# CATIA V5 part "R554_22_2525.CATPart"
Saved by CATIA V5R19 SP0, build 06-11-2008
Material "Steel": density 7860 kg/m3, Young's modulus 2e+11 Pa, Poisson ratio 0.266, thermal expansion 1.17e-05 1/K
Bounding box of the stored display mesh (mm): x -12.582 to 12.582, y -12.358 to 12.439, z 0.001 to 96
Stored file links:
  G:\Podręcznik\CD\Narzędzia\Arkusz Excel\Modele narzędzi\R554.22-2525.CATPart
  C:\Program Files\Dassault Systemes\B19\intel_a\startup\materials\Catalog.CATMaterial
  F:\OSTATNIE\DesignTable_R.xls
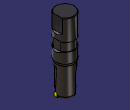
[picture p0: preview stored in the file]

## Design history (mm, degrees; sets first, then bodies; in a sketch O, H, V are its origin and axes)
Parameters
  CuttingType = "CUTTER"
  d = 25 mm {design table}
  D = 25 mm {design table}
  L = 96 mm {design table}
  l = 56 mm {design table}
  alfa = 15 deg {design table}
  gammap = 4 deg {design table}
  S = 3.18 mm {design table}
  rp = 5 mm
  x = 0.6282 mm {design table}
  gammaf = -2 deg {design table}
  z = 2 {design table}
  kat_miedzy_plytkami = 180 deg {design table}
  `dp'` = 9.9756 mm
Body1 "HOLDER" (main body), material "Steel"
  Sketch1 "sketch" on yz-plane, origin (0, 0, 0), H (0, 1, 0), V (0, 0, 1)
    line L1 (0, 0.6282) -> (7.5, 0.6282)
    line L2 (11.5, 4.6282) -> (11.5, 40)
    point P2 (11.5, 40)
    line L3 (11.5, 40) -> (11.5, 40)
    point P3 (12.5, 40)
    line L4 (12.5, 43.2077) -> (12.5, 56.8)
    point P4 (12.5, 56.8)
    line L5 (12.5, 56.8) -> (11.5, 56.8)
    line L6 (11.5, 56.8) -> (11.5, 68)
    line L7 (11.5, 68) -> (12.5, 68)
    point P7 (12.5, 68)
    line L8 (12.5, 68) -> (12.5, 95.2929)
    line L9 (12.5, 95.2929) -> (11.7929, 96)
    line L10 (11.7929, 96) -> (0, 96)
    point P10 (0, 96)
    line L11 (0, 96) -> (0, 0.6282)
    construction line L12 (0, -29.1199) -> (0, 199.3445)
    point P11 (0, -29.1199)
    line L13 (11.5, 40) -> (12.5, 43.2077)
    point P13 (11.5, 40)
    arc A1 centre (7.5, 4.6282) radius 4 from (11.5, 4.6282) to (7.5, 0.6282) cw
    point P17 (7.5, 4.6282)
    length L6 = 11.2 {= 0.2*l}
    distance P2 H = 40 {= L-l}
    length L9 = 1
    angle L8 L9 = 45
    distance L6 L8 = 1
    distance L8 L11 = 12.5 {= d/2}
    distance L10 L7 = 28 {= 0.5*l}
    distance P3 P4 = 16.8 {= 0.3*l}
    length L13 = 3.36 {= 0.2*(0.3*l)}
    distance L1 H = 0.6282 {= x}
    radius A1 = 4 {= 0.8*rp}
    distance P17 L11 = 7.5 {= D/2-rp}
    vertical: L2 V, L4 V, L6 V, L8 V, L11 V, L12 V
    horizontal: L3 H, L5 H, L7 H, L10 H
    coincidence: P7 L4, P10 V, P11 V, L3 P3, L4 P3, P2 P13
    tangency: A1 L2, A1 L1
  Shaft1: profile Sketch1, axis Z axis, angle 360
  Plane1: type Offset, Offset 2, RefPlane zx-plane
  Sketch2 on Plane1, origin (0, 2, 0), H (-1, 0, 0), V (0, 0, 1)
    line L1 (0, 0) -> (4.2605, 0)
    horizontal: L1 H
  Plane2 "gammap": type Angle, Angle -4 {= -gammap}, Direction Sketch2, RefPlane Plane1
  Sketch3 on zx-plane, origin (0, 0, 0), H (-1, 0, 0), V (0, 0, 1)
    line L1 (-10.5, 96) -> (-10.5, 77.6)
    line L2 (-10.5, 77.6) -> (-12.5, 75.6)
    line L3 (-12.5, 75.6) -> (-12.5, 70)
    line L4 (-12.5, 70) -> (-10.5, 68)
    point P5 (-10.5, 68)
    line L5 (-10.5, 68) -> (-10.5, 56.8)
    point P6 (-10.5, 56.8)
    line L6 (-10.5, 56.8) -> (-12.5, 54.8)
    point P7 (-12.5, 54.8)
    line L7 (-12.5, 54.8) -> (-16.5, 54.8)
    line L8 (-16.5, 54.8) -> (-16.5, 96)
    line L9 (-16.5, 96) -> (-10.5, 96)
    reference projected line E1 (-9.2929, 96) -> (9.2929, 96) from edge [face of Shaft1 from Sketch1.L9 | face of Shaft1 from Sketch1.L10]
    reference projected line E2 (-10, 68) -> (10, 68) from edge [face of Shaft1 from Sketch1.L7 | face of Shaft1 from Sketch1.L8]
    reference projected line E3 (-10, 56.8) -> (10, 56.8) from edge [face of Shaft1 from Sketch1.L4 | face of Shaft1 from Sketch1.L5]
    reference projected line E4 through (0, 0) direction (0, 1) from axis of face of Shaft1 from Sketch1.L8
    distance L3 L1 = 2
    angle L2 L1 = 45
    angle L6 L5 = 45
    distance L1 L8 = 6
    distance E4 L3 = 12.5 {= d/2}
    distance P7 L5 = 2
    length L3 = 5.6 {= 0.1*l}
    vertical: L1 V, L3 V, L5 V, L8 V
    perpendicularity: L4 L2
    coincidence: P7 L3, L9 E1, P5 E2, P6 E3
    horizontal: L7 H, L9 H
  Pocket1: profile Sketch3, direction (0, -1, 0), length 20, mirrored extent
  Sketch4 on Plane2, origin (0, 1.9903, 0.1392), H (-1, 0, 0), V (0, -0.0698, 0.9976)
    line L1 (12.5, 13.7491) -> (12.5, 0)
    point P1 (12.5, 0)
    distance V L1 = 12.5 {= D/2}
    coincidence: P1 H
    vertical: L1 V
  Plane3 "gammaf": type Angle, Angle -2 {= gammaf}, Direction Sketch4, RefPlane Plane2
  Plane4: type Offset, Offset 12.5 {= D/2}, RefPlane zx-plane
  Sketch5 on Plane4, origin (0, 12.5, 0), H (-1, 0, 0), V (0, 0, 1)
    point P1 (2.5, 0)
    line L1 (2.5, 0) -> (2.5, 25.1678)
    arc A1 centre (14.5, 25.1678) radius 12 from (2.5, 25.1678) to (12.5, 37) cw
    point P4 (12.5, 37)
    line L2 (12.5, 37) -> (12.5, 0)
    point P5 (12.5, 0)
    line L3 (12.5, 0) -> (2.5, 0)
    reference projected point E1 (0, 4.6282) from edge
    reference projected line E2 (-11.5, 40) -> (11.5, 40) from edge [face of Shaft1 from Sketch1.L2 | face of Shaft1 from Sketch1.L13]
    distance E1 L2 = 12.5 {= D/2}
    radius A1 = 12
    distance E2 P4 = 3
    distance L1 L2 = 10 {= 2*rp}
    coincidence: P1 H, P5 H
    vertical: L1 V, L2 V
    horizontal: L3 H
    tangency: A1 L1
  Pocket2: profile Sketch5, direction (0, -1, 0), up to Plane3
  CircPattern1: of Pocket2, instances 2 {= z}, angular step 180 {= kat_miedzy_plytkami}, axis from Z axis
  Sketch6 on Plane3, origin (-0.0848, 2.4228, 0.1694), H (-0.9994, -0.035, 0), V (0.0024, -0.0697, 0.9976)
    line L1 (12.5, 0) -> (12.5, 6.1909)
    point P1 (12.5, 0)
    distance V L1 = 12.5 {= D/2}
    coincidence: P1 H
    vertical: L1 V
  Plane5: type Angle, Angle 90, Direction Sketch6, RefPlane Plane3
  Plane6: type Offset, Offset 5 {= rp}, RefPlane Plane5, reversed
  Sketch7 on Plane6, origin (-7.4954, -0.2624, 0), H (0.035, -0.9994, 0), V (0, 0, 1)
    point P1 (-2.9373, 0)
    line L1 (-2.9373, 0) -> (-2.5887, 4.9878)
    line L2 (-2.5887, 4.9878) -> (0.5835, 4.7661)
    line L3 (0.5835, 4.7661) -> (0.2944, 0.6283)
    line L4 (0.2944, 0.6283) -> (-2.9373, 0)
    axis line L5 (-2.9373, 0) -> (2.8409, -0.4038)
    reference projected line E1 (-0.6773, 25.1678) -> (-2.4361, 0) from edge [end face of Pocket2 | face of Pocket2 from Sketch5.L1]
    reference projected line E2 (-0.6773, 25.1678) -> (-2.4361, 0) from edge [end face of Pocket2 | face of Pocket2 from Sketch5.L1]
    distance L1 L3 = 3.18 {= S}
    length L1 = 5 {= rp}
    angle L5 L4 = 15 {= alfa}
    distance L1 E2 = 0.5
    coincidence: P1 H
    perpendicularity: L2 L1
    parallelism: L5 L2, L1 E1
  Groove1: profile Sketch7, axis Sketch7.L2, angle 360
  CircPattern2: of Groove1, instances 2 {= z}, angular step 180 {= kat_miedzy_plytkami}, axis from Z axis
Body2 "CUTTER"
  Sketch8 "CUT" on yz-plane, origin (0, 0, 0), H (0, 1, 0), V (0, 0, 1)
    point P1 (7.5, 5)
    point P2 (0, 0.6282)
    line L1 (0, 0.6282) -> (5.0737, 0.6282)
    arc A1 centre (7.5, 5) radius 5 from (5.0737, 0.6282) to (11.5, 8) ccw
    point P4 (7.5, 5)
    point P5 (11.5, 8)
    line L2 (11.5, 8) -> (0, 8)
    point P6 (0, 8)
    line L3 (0, 8) -> (0, 0.6282)
    axis line L4 (0, 8) -> (12.5, 8)
    point P7 (12.5, 8)
    distance P1 H = 5 {= rp}
    distance P1 V = 7.5 {= D/2-rp}
    distance H L1 = 0.6282 {= x}
    length L4 = 12.5 {= D/2}
    distance P7 P5 = 1
    coincidence: P2 V, P6 V, P4 P1
    horizontal: L1 H, L2 H, L4 H
    vertical: L3 V
    tangency: A1 H
  Sketch9 "NOCUT" on yz-plane, origin (0, 0, 0), H (0, 1, 0), V (0, 0, 1)
    point P1 (0, 8)
    line L1 (0, 8) -> (11.5, 8)
    point P2 (11.5, 8)
    line L2 (11.5, 8) -> (11.5, 40)
    line L3 (11.5, 40) -> (12.5, 40)
    line L4 (12.5, 40) -> (12.5, 56.8)
    line L5 (12.5, 56.8) -> (11.5, 56.8)
    line L6 (11.5, 56.8) -> (11.5, 68)
    line L7 (11.5, 68) -> (12.5, 68)
    point P8 (12.5, 68)
    line L8 (12.5, 68) -> (12.5, 96)
    line L9 (12.5, 96) -> (0, 96)
    point P10 (0, 96)
    line L10 (0, 96) -> (0, 8)
    reference projected line E1 (11.5, 8) -> (0, 8) from Sketch8.L2
    reference projected point E2 (11.5, 8) from vertex [element of Sketch8 | element of Sketch8]
    reference projected line E3 (-11.7929, 96) -> (11.7929, 96) from edge [face of Shaft1 from Sketch1.L9 | face of Shaft1 from Sketch1.L10]
    length L8 = 28 {= 0.5*l}
    length L6 = 11.2 {= 0.2*l}
    length L4 = 16.8 {= 0.3*l}
    distance L8 L10 = 12.5 {= d/2}
    distance L6 L8 = 1
    coincidence: P1 V, P8 L4, P10 V, E1 L1, P2 E2, L9 E3
    horizontal: L1 H, L3 H, L5 H, L7 H, L9 H
    vertical: L2 V, L4 V, L6 V, L8 V, L10 V
  Shaft2: profile Sketch7, axis Sketch7.L2, angle 360
  CircPattern3: of Shaft2, instances 2 {= z}, angular step 180 {= kat_miedzy_plytkami}, axis from Z axis
Relations
  design table, configuration 1, drives d, D, L, l, alfa, gammap, S, x, gammaf, z, kat_miedzy_plytkami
